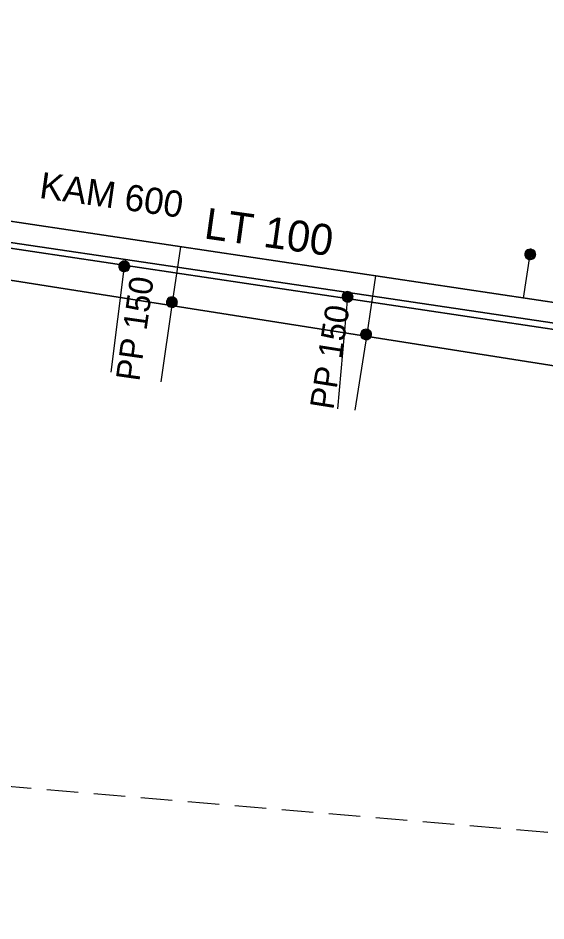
# Model space of a CAD drawing. Extents: x -866761 to -866592, y -1013996 to -1013877.
# Drawn here: x -866682.75 to -866660.58, y -1013995.54 to -1013957.66 of the extents above; entities that cross this region are included whole.
import ezdxf

# ---------------------------------------------------------------- set-up
doc = ezdxf.new("R2010")
doc.units = 0
doc.header["$LTSCALE"] = 0.44
doc.linetypes.add('MEDIUM_DASHED', pattern=[4.5, 3, -1.5])
for name, color, linetype, lineweight in [('1', 7, 'Continuous', 35), ('12', 7, 'Continuous', 13), ('21', 7, 'Continuous', 35), ('23', 7, 'Continuous', 25), ('25', 7, 'Continuous', 13), ('3', 7, 'Continuous', 25), ('32', 7, 'Continuous', 13), ('62', 7, 'MEDIUM_DASHED', 25)]:
    doc.layers.add(name, color=color, linetype=linetype, lineweight=lineweight)

msp = doc.modelspace()

# ---------------------------------------------------------------- linework, layer by layer
at = {"layer": '1'}
msp.add_line((-866612.967, -1013977.763), (-866734.931, -1013959.586), dxfattribs=at)
for points in [[(-866612.815, -1013977.108), (-866621.035, -1013976.325), (-866621.378, -1013976.297), (-866626.243, -1013975.519), (-866632.94, -1013974.51), (-866645.03, -1013972.86), (-866647.305, -1013972.501), (-866654.48, -1013971.31), (-866668.882, -1013969.171), (-866678.229, -1013967.78), (-866685.446, -1013966.718), (-866689.8, -1013966.06), (-866697.865, -1013964.927), (-866723.097, -1013961.352), (-866726.923, -1013960.77), (-866727.214, -1013960.734), (-866737.38, -1013959.64), (-866746.09, -1013958.48), (-866747.84, -1013958.25), (-866748.13, -1013958.99), (-866750.15, -1013958.69)], [(-866613.338, -1013979.363), (-866624.951, -1013977.802), (-866715.256, -1013963.593), (-866735.102, -1013960.577)]]:
    msp.add_lwpolyline(points, dxfattribs=at)
at = {"layer": '12'}
for points in [[(-866678.054, -1013968.073), (-866678.061, -1013968.021), (-866678.078, -1013967.971), (-866678.107, -1013967.927), (-866678.144, -1013967.89), (-866678.189, -1013967.863), (-866678.239, -1013967.846), (-866678.292, -1013967.842), (-866678.343, -1013967.849), (-866678.392, -1013967.868), (-866678.436, -1013967.897), (-866678.472, -1013967.936), (-866678.498, -1013967.981), (-866678.514, -1013968.032), (-866678.517, -1013968.084), (-866678.509, -1013968.136), (-866678.489, -1013968.185), (-866678.458, -1013968.228), (-866678.419, -1013968.262), (-866678.373, -1013968.288), (-866678.321, -1013968.302), (-866678.269, -1013968.304), (-866678.218, -1013968.294), (-866678.169, -1013968.273), (-866678.127, -1013968.242), (-866678.093, -1013968.201), (-866678.069, -1013968.155), (-866678.056, -1013968.104)], [(-866678.085, -1013968.073), (-866678.091, -1013968.024), (-866678.108, -1013967.978), (-866678.136, -1013967.938), (-866678.173, -1013967.906), (-866678.217, -1013967.884), (-866678.265, -1013967.873), (-866678.314, -1013967.873), (-866678.36, -1013967.886), (-866678.404, -1013967.91), (-866678.44, -1013967.943), (-866678.467, -1013967.984), (-866678.483, -1013968.031), (-866678.487, -1013968.08), (-866678.48, -1013968.128), (-866678.461, -1013968.173), (-866678.431, -1013968.213), (-866678.392, -1013968.244), (-866678.348, -1013968.264), (-866678.301, -1013968.274), (-866678.252, -1013968.272), (-866678.205, -1013968.257), (-866678.162, -1013968.232), (-866678.127, -1013968.198), (-866678.102, -1013968.156), (-866678.088, -1013968.109)], [(-866678.115, -1013968.073), (-866678.12, -1013968.028), (-866678.137, -1013967.986), (-866678.166, -1013967.951), (-866678.201, -1013967.924), (-866678.244, -1013967.907), (-866678.289, -1013967.902), (-866678.333, -1013967.908), (-866678.375, -1013967.927), (-866678.409, -1013967.955), (-866678.436, -1013967.992), (-866678.453, -1013968.034), (-866678.456, -1013968.079), (-866678.45, -1013968.124), (-866678.431, -1013968.165), (-866678.402, -1013968.199), (-866678.365, -1013968.225), (-866678.321, -1013968.241), (-866678.277, -1013968.244), (-866678.232, -1013968.236), (-866678.191, -1013968.216), (-866678.157, -1013968.187), (-866678.132, -1013968.149), (-866678.118, -1013968.106)], [(-866678.145, -1013968.073), (-866678.149, -1013968.032), (-866678.168, -1013967.995), (-866678.195, -1013967.964), (-866678.23, -1013967.943), (-866678.27, -1013967.932), (-866678.311, -1013967.934), (-866678.35, -1013967.947), (-866678.384, -1013967.971), (-866678.409, -1013968.003), (-866678.424, -1013968.041), (-866678.426, -1013968.082), (-866678.419, -1013968.122), (-866678.399, -1013968.158), (-866678.37, -1013968.187), (-866678.333, -1013968.206), (-866678.293, -1013968.214), (-866678.252, -1013968.21), (-866678.213, -1013968.195), (-866678.181, -1013968.169), (-866678.159, -1013968.135), (-866678.146, -1013968.096)], [(-866678.174, -1013968.073), (-866678.179, -1013968.037), (-866678.198, -1013968.005), (-866678.223, -1013967.98), (-866678.257, -1013967.965), (-866678.294, -1013967.962), (-866678.328, -1013967.97), (-866678.36, -1013967.99), (-866678.382, -1013968.018), (-866678.396, -1013968.052), (-866678.396, -1013968.089), (-866678.385, -1013968.124), (-866678.364, -1013968.153), (-866678.333, -1013968.174), (-866678.299, -1013968.184), (-866678.262, -1013968.182), (-866678.228, -1013968.168), (-866678.201, -1013968.145), (-866678.181, -1013968.113), (-866678.174, -1013968.078)], [(-866678.205, -1013968.073), (-866678.21, -1013968.042), (-866678.227, -1013968.016), (-866678.252, -1013967.999), (-866678.282, -1013967.992), (-866678.314, -1013967.996), (-866678.341, -1013968.013), (-866678.358, -1013968.037), (-866678.367, -1013968.068), (-866678.363, -1013968.098), (-866678.348, -1013968.126), (-866678.323, -1013968.145), (-866678.294, -1013968.154), (-866678.262, -1013968.151), (-866678.235, -1013968.137), (-866678.215, -1013968.113), (-866678.205, -1013968.084)], [(-866678.235, -1013968.073), (-866678.24, -1013968.049), (-866678.257, -1013968.031), (-866678.279, -1013968.022), (-866678.304, -1013968.025), (-866678.325, -1013968.039), (-866678.336, -1013968.061), (-866678.336, -1013968.086), (-866678.323, -1013968.107), (-866678.304, -1013968.121), (-866678.279, -1013968.124), (-866678.255, -1013968.115), (-866678.24, -1013968.097)], [(-866678.265, -1013968.073), (-866678.27, -1013968.058), (-866678.284, -1013968.052), (-866678.299, -1013968.056), (-866678.306, -1013968.07), (-866678.303, -1013968.085), (-866678.289, -1013968.094), (-866678.274, -1013968.091), (-866678.265, -1013968.079)], [(-866668.679, -1013969.35), (-866668.685, -1013969.298), (-866668.702, -1013969.248), (-866668.731, -1013969.204), (-866668.768, -1013969.167), (-866668.813, -1013969.14), (-866668.863, -1013969.123), (-866668.916, -1013969.119), (-866668.968, -1013969.126), (-866669.017, -1013969.145), (-866669.06, -1013969.174), (-866669.096, -1013969.213), (-866669.122, -1013969.258), (-866669.138, -1013969.309), (-866669.141, -1013969.361), (-866669.133, -1013969.413), (-866669.113, -1013969.462), (-866669.082, -1013969.505), (-866669.043, -1013969.539), (-866668.997, -1013969.565), (-866668.946, -1013969.579), (-866668.893, -1013969.581), (-866668.842, -1013969.571), (-866668.794, -1013969.55), (-866668.751, -1013969.519), (-866668.717, -1013969.478), (-866668.693, -1013969.432), (-866668.681, -1013969.381)], [(-866668.709, -1013969.35), (-866668.715, -1013969.301), (-866668.732, -1013969.255), (-866668.76, -1013969.215), (-866668.797, -1013969.183), (-866668.841, -1013969.161), (-866668.889, -1013969.15), (-866668.938, -1013969.15), (-866668.985, -1013969.163), (-866669.028, -1013969.187), (-866669.064, -1013969.22), (-866669.091, -1013969.261), (-866669.107, -1013969.308), (-866669.111, -1013969.357), (-866669.104, -1013969.405), (-866669.085, -1013969.45), (-866669.055, -1013969.49), (-866669.017, -1013969.521), (-866668.973, -1013969.541), (-866668.925, -1013969.551), (-866668.876, -1013969.549), (-866668.829, -1013969.534), (-866668.786, -1013969.509), (-866668.752, -1013969.475), (-866668.726, -1013969.433), (-866668.712, -1013969.386)], [(-866668.739, -1013969.35), (-866668.745, -1013969.305), (-866668.762, -1013969.263), (-866668.79, -1013969.228), (-866668.826, -1013969.201), (-866668.868, -1013969.184), (-866668.913, -1013969.179), (-866668.958, -1013969.185), (-866668.999, -1013969.204), (-866669.034, -1013969.232), (-866669.061, -1013969.269), (-866669.077, -1013969.311), (-866669.081, -1013969.356), (-866669.074, -1013969.401), (-866669.055, -1013969.442), (-866669.026, -1013969.476), (-866668.989, -1013969.502), (-866668.946, -1013969.518), (-866668.901, -1013969.521), (-866668.856, -1013969.513), (-866668.816, -1013969.493), (-866668.782, -1013969.464), (-866668.756, -1013969.426), (-866668.742, -1013969.383)], [(-866668.769, -1013969.35), (-866668.774, -1013969.309), (-866668.792, -1013969.272), (-866668.819, -1013969.241), (-866668.854, -1013969.22), (-866668.894, -1013969.209), (-866668.935, -1013969.211), (-866668.974, -1013969.224), (-866669.008, -1013969.248), (-866669.033, -1013969.28), (-866669.048, -1013969.318), (-866669.051, -1013969.359), (-866669.043, -1013969.399), (-866669.023, -1013969.435), (-866668.994, -1013969.464), (-866668.957, -1013969.483), (-866668.917, -1013969.491), (-866668.876, -1013969.487), (-866668.838, -1013969.472), (-866668.806, -1013969.446), (-866668.783, -1013969.412), (-866668.77, -1013969.373)], [(-866668.799, -1013969.35), (-866668.804, -1013969.314), (-866668.822, -1013969.282), (-866668.848, -1013969.257), (-866668.882, -1013969.242), (-866668.918, -1013969.239), (-866668.953, -1013969.247), (-866668.984, -1013969.267), (-866669.007, -1013969.295), (-866669.02, -1013969.329), (-866669.02, -1013969.366), (-866669.009, -1013969.401), (-866668.988, -1013969.43), (-866668.958, -1013969.451), (-866668.923, -1013969.461), (-866668.886, -1013969.459), (-866668.852, -1013969.445), (-866668.825, -1013969.422), (-866668.806, -1013969.39), (-866668.799, -1013969.355)], [(-866668.829, -1013969.35), (-866668.834, -1013969.319), (-866668.851, -1013969.293), (-866668.877, -1013969.276), (-866668.907, -1013969.269), (-866668.938, -1013969.273), (-866668.965, -1013969.29), (-866668.983, -1013969.314), (-866668.991, -1013969.345), (-866668.987, -1013969.375), (-866668.972, -1013969.403), (-866668.948, -1013969.422), (-866668.918, -1013969.431), (-866668.887, -1013969.428), (-866668.859, -1013969.414), (-866668.839, -1013969.39), (-866668.829, -1013969.361)], [(-866668.859, -1013969.35), (-866668.864, -1013969.326), (-866668.881, -1013969.308), (-866668.904, -1013969.299), (-866668.928, -1013969.302), (-866668.949, -1013969.316), (-866668.96, -1013969.338), (-866668.96, -1013969.363), (-866668.948, -1013969.384), (-866668.928, -1013969.398), (-866668.903, -1013969.401), (-866668.88, -1013969.392), (-866668.864, -1013969.374)], [(-866668.889, -1013969.35), (-866668.894, -1013969.335), (-866668.909, -1013969.329), (-866668.924, -1013969.333), (-866668.931, -1013969.347), (-866668.927, -1013969.362), (-866668.914, -1013969.371), (-866668.899, -1013969.368), (-866668.889, -1013969.356)]]:
    msp.add_lwpolyline(points, close=True, dxfattribs=at)
at = {"layer": '21'}
msp.add_line((-866709.04, -1013962.31), (-866647.459, -1013971.5), dxfattribs=at)
at = {"layer": '23'}
msp.add_line((-866661.514, -1013969.403), (-866661.239, -1013967.57), dxfattribs=at)
for points in [[(-866675.92, -1013967.253), (-866676.27, -1013969.6), (-866676.744, -1013972.917)], [(-866667.734, -1013968.474), (-866668.1, -1013970.93), (-866668.597, -1013974.112)]]:
    msp.add_lwpolyline(points, dxfattribs=at)
at = {"layer": '25'}
for points in [[(-866661.007, -1013967.57), (-866661.014, -1013967.518), (-866661.031, -1013967.468), (-866661.059, -1013967.424), (-866661.097, -1013967.387), (-866661.142, -1013967.36), (-866661.191, -1013967.343), (-866661.245, -1013967.339), (-866661.296, -1013967.346), (-866661.345, -1013967.365), (-866661.389, -1013967.394), (-866661.424, -1013967.433), (-866661.451, -1013967.478), (-866661.467, -1013967.529), (-866661.47, -1013967.581), (-866661.462, -1013967.633), (-866661.441, -1013967.682), (-866661.411, -1013967.725), (-866661.372, -1013967.759), (-866661.326, -1013967.785), (-866661.274, -1013967.799), (-866661.222, -1013967.801), (-866661.171, -1013967.791), (-866661.122, -1013967.77), (-866661.08, -1013967.739), (-866661.046, -1013967.698), (-866661.022, -1013967.652), (-866661.009, -1013967.601)], [(-866661.038, -1013967.57), (-866661.044, -1013967.521), (-866661.061, -1013967.475), (-866661.088, -1013967.435), (-866661.125, -1013967.403), (-866661.169, -1013967.381), (-866661.218, -1013967.37), (-866661.267, -1013967.37), (-866661.313, -1013967.383), (-866661.357, -1013967.407), (-866661.392, -1013967.44), (-866661.419, -1013967.481), (-866661.436, -1013967.528), (-866661.44, -1013967.577), (-866661.433, -1013967.625), (-866661.414, -1013967.67), (-866661.384, -1013967.71), (-866661.345, -1013967.741), (-866661.301, -1013967.761), (-866661.254, -1013967.771), (-866661.205, -1013967.769), (-866661.157, -1013967.754), (-866661.115, -1013967.729), (-866661.08, -1013967.695), (-866661.054, -1013967.653), (-866661.041, -1013967.606)], [(-866661.068, -1013967.57), (-866661.073, -1013967.525), (-866661.09, -1013967.483), (-866661.119, -1013967.448), (-866661.154, -1013967.421), (-866661.196, -1013967.404), (-866661.242, -1013967.399), (-866661.286, -1013967.405), (-866661.328, -1013967.424), (-866661.362, -1013967.452), (-866661.389, -1013967.489), (-866661.406, -1013967.531), (-866661.409, -1013967.576), (-866661.402, -1013967.621), (-866661.384, -1013967.662), (-866661.355, -1013967.696), (-866661.318, -1013967.722), (-866661.274, -1013967.738), (-866661.23, -1013967.741), (-866661.184, -1013967.733), (-866661.144, -1013967.713), (-866661.11, -1013967.684), (-866661.085, -1013967.646), (-866661.071, -1013967.603)], [(-866661.098, -1013967.57), (-866661.102, -1013967.529), (-866661.12, -1013967.492), (-866661.147, -1013967.461), (-866661.183, -1013967.44), (-866661.223, -1013967.429), (-866661.264, -1013967.431), (-866661.303, -1013967.444), (-866661.337, -1013967.468), (-866661.362, -1013967.5), (-866661.377, -1013967.538), (-866661.379, -1013967.579), (-866661.372, -1013967.619), (-866661.352, -1013967.655), (-866661.323, -1013967.684), (-866661.286, -1013967.703), (-866661.245, -1013967.711), (-866661.205, -1013967.707), (-866661.166, -1013967.692), (-866661.134, -1013967.666), (-866661.112, -1013967.632), (-866661.098, -1013967.593)], [(-866661.127, -1013967.57), (-866661.132, -1013967.534), (-866661.151, -1013967.502), (-866661.176, -1013967.477), (-866661.21, -1013967.462), (-866661.247, -1013967.459), (-866661.281, -1013967.467), (-866661.313, -1013967.487), (-866661.335, -1013967.515), (-866661.348, -1013967.549), (-866661.348, -1013967.586), (-866661.338, -1013967.621), (-866661.316, -1013967.65), (-866661.286, -1013967.671), (-866661.252, -1013967.681), (-866661.215, -1013967.679), (-866661.181, -1013967.665), (-866661.154, -1013967.642), (-866661.134, -1013967.61), (-866661.127, -1013967.575)], [(-866661.157, -1013967.57), (-866661.163, -1013967.539), (-866661.179, -1013967.513), (-866661.205, -1013967.496), (-866661.235, -1013967.489), (-866661.267, -1013967.493), (-866661.294, -1013967.51), (-866661.311, -1013967.534), (-866661.32, -1013967.565), (-866661.316, -1013967.595), (-866661.301, -1013967.623), (-866661.276, -1013967.642), (-866661.247, -1013967.651), (-866661.215, -1013967.648), (-866661.188, -1013967.634), (-866661.168, -1013967.61), (-866661.157, -1013967.581)], [(-866661.188, -1013967.57), (-866661.193, -1013967.546), (-866661.21, -1013967.528), (-866661.232, -1013967.519), (-866661.257, -1013967.522), (-866661.277, -1013967.536), (-866661.289, -1013967.558), (-866661.289, -1013967.583), (-866661.276, -1013967.604), (-866661.257, -1013967.618), (-866661.232, -1013967.621), (-866661.208, -1013967.612), (-866661.193, -1013967.594)], [(-866661.218, -1013967.57), (-866661.223, -1013967.555), (-866661.237, -1013967.549), (-866661.252, -1013967.553), (-866661.259, -1013967.567), (-866661.255, -1013967.582), (-866661.242, -1013967.591), (-866661.227, -1013967.588), (-866661.218, -1013967.576)]]:
    msp.add_lwpolyline(points, close=True, dxfattribs=at)
at = {"layer": '3'}
for points in [[(-866678.229, -1013967.78), (-866678.286, -1013968.073), (-866678.85, -1013972.52)], [(-866668.882, -1013969.171), (-866668.91, -1013969.35), (-866669.33, -1013974.05)]]:
    msp.add_lwpolyline(points, dxfattribs=at)
at = {"layer": '32'}
for points in [[(-866676.056, -1013969.578), (-866676.062, -1013969.526), (-866676.079, -1013969.476), (-866676.108, -1013969.432), (-866676.145, -1013969.395), (-866676.19, -1013969.368), (-866676.24, -1013969.351), (-866676.293, -1013969.347), (-866676.345, -1013969.354), (-866676.394, -1013969.373), (-866676.437, -1013969.402), (-866676.473, -1013969.441), (-866676.499, -1013969.486), (-866676.515, -1013969.537), (-866676.518, -1013969.589), (-866676.51, -1013969.641), (-866676.49, -1013969.69), (-866676.459, -1013969.733), (-866676.42, -1013969.767), (-866676.374, -1013969.793), (-866676.323, -1013969.807), (-866676.27, -1013969.809), (-866676.219, -1013969.799), (-866676.171, -1013969.778), (-866676.128, -1013969.747), (-866676.094, -1013969.706), (-866676.07, -1013969.66), (-866676.058, -1013969.609)], [(-866676.086, -1013969.578), (-866676.092, -1013969.529), (-866676.109, -1013969.483), (-866676.137, -1013969.443), (-866676.174, -1013969.411), (-866676.218, -1013969.389), (-866676.266, -1013969.378), (-866676.315, -1013969.378), (-866676.362, -1013969.391), (-866676.405, -1013969.415), (-866676.441, -1013969.448), (-866676.468, -1013969.489), (-866676.484, -1013969.536), (-866676.488, -1013969.585), (-866676.481, -1013969.633), (-866676.462, -1013969.678), (-866676.432, -1013969.718), (-866676.394, -1013969.749), (-866676.35, -1013969.769), (-866676.302, -1013969.779), (-866676.253, -1013969.777), (-866676.206, -1013969.762), (-866676.163, -1013969.737), (-866676.129, -1013969.703), (-866676.103, -1013969.661), (-866676.089, -1013969.614)], [(-866676.116, -1013969.578), (-866676.122, -1013969.533), (-866676.139, -1013969.491), (-866676.167, -1013969.456), (-866676.203, -1013969.429), (-866676.245, -1013969.412), (-866676.29, -1013969.407), (-866676.335, -1013969.413), (-866676.376, -1013969.432), (-866676.411, -1013969.46), (-866676.438, -1013969.497), (-866676.454, -1013969.539), (-866676.458, -1013969.584), (-866676.451, -1013969.629), (-866676.432, -1013969.67), (-866676.403, -1013969.704), (-866676.366, -1013969.73), (-866676.323, -1013969.746), (-866676.278, -1013969.749), (-866676.233, -1013969.741), (-866676.193, -1013969.721), (-866676.159, -1013969.692), (-866676.133, -1013969.654), (-866676.119, -1013969.611)], [(-866676.146, -1013969.578), (-866676.151, -1013969.537), (-866676.169, -1013969.5), (-866676.196, -1013969.469), (-866676.231, -1013969.448), (-866676.271, -1013969.437), (-866676.312, -1013969.439), (-866676.351, -1013969.452), (-866676.385, -1013969.476), (-866676.41, -1013969.508), (-866676.425, -1013969.546), (-866676.428, -1013969.587), (-866676.42, -1013969.627), (-866676.4, -1013969.663), (-866676.371, -1013969.692), (-866676.334, -1013969.711), (-866676.294, -1013969.719), (-866676.253, -1013969.715), (-866676.215, -1013969.7), (-866676.183, -1013969.674), (-866676.16, -1013969.64), (-866676.147, -1013969.601)], [(-866676.176, -1013969.578), (-866676.181, -1013969.542), (-866676.199, -1013969.51), (-866676.225, -1013969.485), (-866676.259, -1013969.47), (-866676.295, -1013969.467), (-866676.33, -1013969.475), (-866676.361, -1013969.495), (-866676.384, -1013969.523), (-866676.397, -1013969.557), (-866676.397, -1013969.594), (-866676.386, -1013969.629), (-866676.365, -1013969.658), (-866676.335, -1013969.679), (-866676.3, -1013969.689), (-866676.263, -1013969.687), (-866676.229, -1013969.673), (-866676.202, -1013969.65), (-866676.183, -1013969.618), (-866676.176, -1013969.583)], [(-866676.206, -1013969.578), (-866676.211, -1013969.547), (-866676.228, -1013969.521), (-866676.254, -1013969.504), (-866676.284, -1013969.497), (-866676.315, -1013969.501), (-866676.342, -1013969.518), (-866676.36, -1013969.542), (-866676.368, -1013969.573), (-866676.364, -1013969.603), (-866676.349, -1013969.631), (-866676.325, -1013969.65), (-866676.295, -1013969.659), (-866676.264, -1013969.656), (-866676.236, -1013969.642), (-866676.216, -1013969.618), (-866676.206, -1013969.589)], [(-866676.236, -1013969.578), (-866676.241, -1013969.554), (-866676.258, -1013969.536), (-866676.281, -1013969.527), (-866676.305, -1013969.53), (-866676.326, -1013969.544), (-866676.337, -1013969.566), (-866676.337, -1013969.591), (-866676.325, -1013969.612), (-866676.305, -1013969.626), (-866676.28, -1013969.629), (-866676.257, -1013969.62), (-866676.241, -1013969.602)], [(-866676.266, -1013969.578), (-866676.271, -1013969.563), (-866676.286, -1013969.557), (-866676.301, -1013969.561), (-866676.308, -1013969.575), (-866676.304, -1013969.59), (-866676.291, -1013969.599), (-866676.276, -1013969.596), (-866676.266, -1013969.584)], [(-866667.899, -1013970.933), (-866667.905, -1013970.881), (-866667.922, -1013970.831), (-866667.951, -1013970.787), (-866667.988, -1013970.75), (-866668.033, -1013970.723), (-866668.083, -1013970.706), (-866668.136, -1013970.702), (-866668.188, -1013970.709), (-866668.237, -1013970.728), (-866668.28, -1013970.757), (-866668.316, -1013970.796), (-866668.342, -1013970.841), (-866668.358, -1013970.892), (-866668.361, -1013970.944), (-866668.353, -1013970.996), (-866668.333, -1013971.045), (-866668.302, -1013971.088), (-866668.263, -1013971.122), (-866668.217, -1013971.148), (-866668.166, -1013971.162), (-866668.113, -1013971.164), (-866668.062, -1013971.154), (-866668.014, -1013971.133), (-866667.971, -1013971.102), (-866667.937, -1013971.061), (-866667.913, -1013971.015), (-866667.901, -1013970.964)], [(-866667.929, -1013970.933), (-866667.935, -1013970.884), (-866667.952, -1013970.838), (-866667.98, -1013970.798), (-866668.017, -1013970.766), (-866668.061, -1013970.744), (-866668.109, -1013970.733), (-866668.158, -1013970.733), (-866668.205, -1013970.746), (-866668.248, -1013970.77), (-866668.284, -1013970.803), (-866668.311, -1013970.844), (-866668.327, -1013970.891), (-866668.331, -1013970.94), (-866668.324, -1013970.988), (-866668.305, -1013971.033), (-866668.275, -1013971.073), (-866668.237, -1013971.104), (-866668.193, -1013971.124), (-866668.145, -1013971.134), (-866668.096, -1013971.132), (-866668.049, -1013971.117), (-866668.006, -1013971.092), (-866667.972, -1013971.058), (-866667.946, -1013971.016), (-866667.932, -1013970.969)], [(-866667.959, -1013970.933), (-866667.965, -1013970.888), (-866667.982, -1013970.846), (-866668.01, -1013970.811), (-866668.046, -1013970.784), (-866668.088, -1013970.767), (-866668.133, -1013970.762), (-866668.178, -1013970.768), (-866668.219, -1013970.787), (-866668.254, -1013970.815), (-866668.281, -1013970.852), (-866668.297, -1013970.894), (-866668.301, -1013970.939), (-866668.294, -1013970.984), (-866668.275, -1013971.025), (-866668.246, -1013971.059), (-866668.209, -1013971.085), (-866668.166, -1013971.101), (-866668.121, -1013971.104), (-866668.076, -1013971.096), (-866668.036, -1013971.076), (-866668.002, -1013971.047), (-866667.976, -1013971.009), (-866667.962, -1013970.966)], [(-866667.989, -1013970.933), (-866667.994, -1013970.892), (-866668.012, -1013970.855), (-866668.039, -1013970.824), (-866668.074, -1013970.803), (-866668.114, -1013970.792), (-866668.155, -1013970.794), (-866668.194, -1013970.807), (-866668.228, -1013970.831), (-866668.253, -1013970.863), (-866668.268, -1013970.901), (-866668.271, -1013970.942), (-866668.263, -1013970.982), (-866668.243, -1013971.018), (-866668.214, -1013971.047), (-866668.177, -1013971.066), (-866668.137, -1013971.074), (-866668.096, -1013971.07), (-866668.058, -1013971.055), (-866668.026, -1013971.029), (-866668.003, -1013970.995), (-866667.99, -1013970.956)], [(-866668.019, -1013970.933), (-866668.024, -1013970.897), (-866668.042, -1013970.865), (-866668.068, -1013970.84), (-866668.102, -1013970.825), (-866668.138, -1013970.822), (-866668.173, -1013970.83), (-866668.204, -1013970.85), (-866668.227, -1013970.878), (-866668.24, -1013970.912), (-866668.24, -1013970.949), (-866668.229, -1013970.984), (-866668.208, -1013971.013), (-866668.178, -1013971.034), (-866668.143, -1013971.044), (-866668.106, -1013971.042), (-866668.072, -1013971.028), (-866668.045, -1013971.005), (-866668.026, -1013970.973), (-866668.019, -1013970.938)], [(-866668.049, -1013970.933), (-866668.054, -1013970.902), (-866668.071, -1013970.876), (-866668.097, -1013970.859), (-866668.127, -1013970.852), (-866668.158, -1013970.856), (-866668.185, -1013970.873), (-866668.203, -1013970.897), (-866668.211, -1013970.928), (-866668.207, -1013970.958), (-866668.192, -1013970.986), (-866668.168, -1013971.005), (-866668.138, -1013971.014), (-866668.107, -1013971.011), (-866668.079, -1013970.997), (-866668.059, -1013970.973), (-866668.049, -1013970.944)], [(-866668.079, -1013970.933), (-866668.084, -1013970.909), (-866668.101, -1013970.891), (-866668.124, -1013970.882), (-866668.148, -1013970.885), (-866668.169, -1013970.899), (-866668.18, -1013970.921), (-866668.18, -1013970.946), (-866668.168, -1013970.967), (-866668.148, -1013970.981), (-866668.123, -1013970.984), (-866668.1, -1013970.975), (-866668.084, -1013970.957)], [(-866668.109, -1013970.933), (-866668.114, -1013970.918), (-866668.129, -1013970.912), (-866668.144, -1013970.916), (-866668.151, -1013970.93), (-866668.147, -1013970.945), (-866668.134, -1013970.954), (-866668.119, -1013970.951), (-866668.109, -1013970.939)]]:
    msp.add_lwpolyline(points, close=True, dxfattribs=at)
at = {"layer": '62'}
msp.add_lwpolyline([(-866747.317, -1013876.568), (-866591.969, -1013887.219), (-866617.09, -1013995.541), (-866760.581, -1013983.282)], close=True, dxfattribs=at)

# ---------------------------------------------------------------- texts
at = {"layer": '1'}
for s, height, p in [('KAM 600 ', 1.1, (-866681.888, -1013965.198)), ('LT 100', 1.3, (-866674.974, -1013966.897))]:
    msp.add_text(s, height=height, rotation=352, dxfattribs=at).set_placement(p)
at = {"layer": '23'}
for rotation, p in [(82, (-866677.654, -1013972.925)), (81, (-866669.508, -1013974.119))]:
    msp.add_text('PP 150', height=1, rotation=rotation, dxfattribs=at).set_placement(p)

doc.saveas('drawing.dxf')
